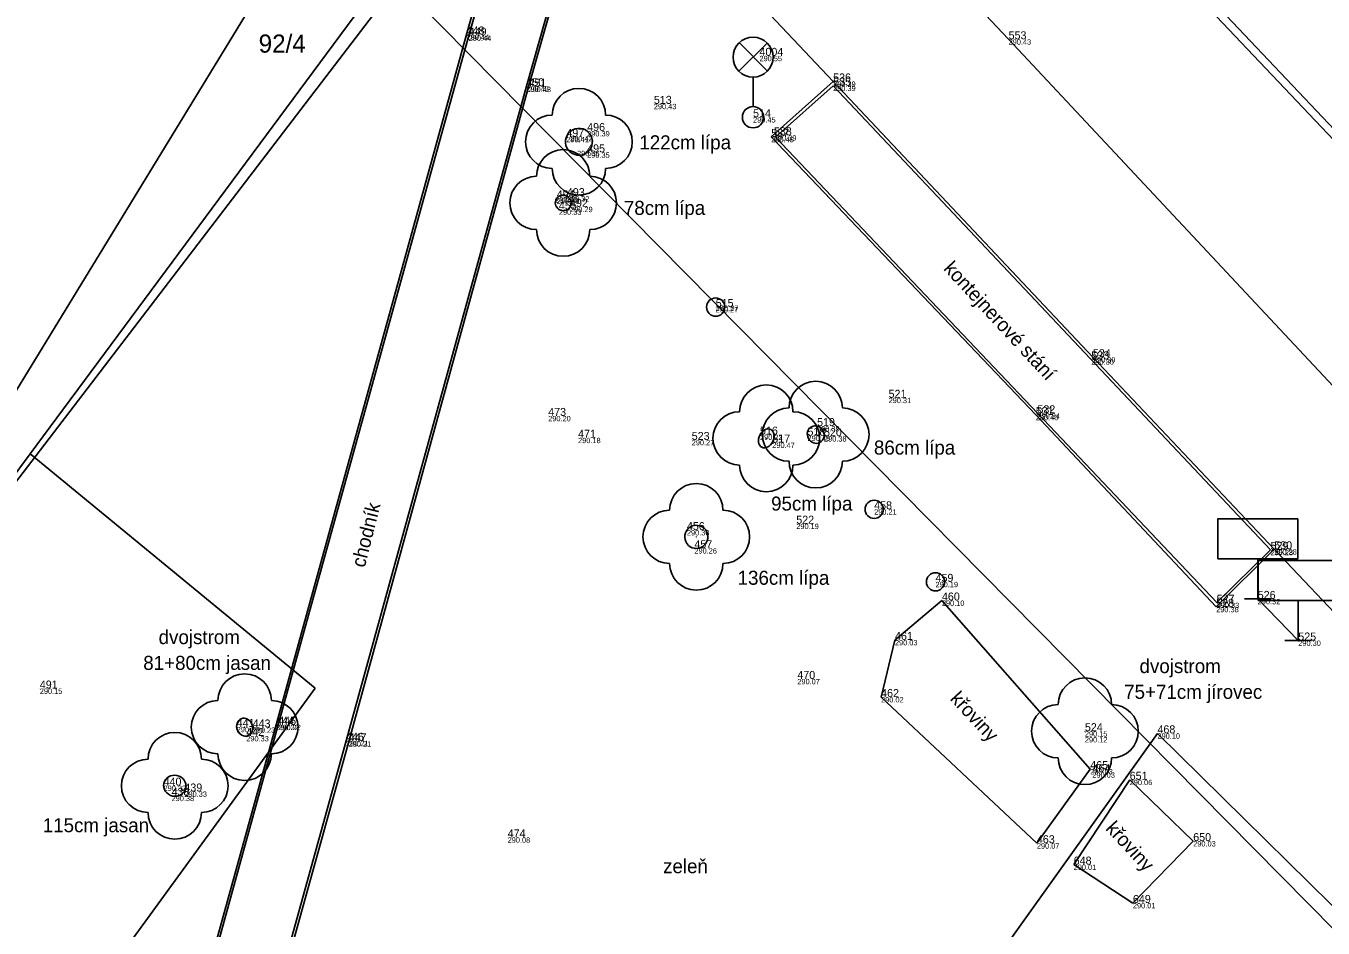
# Model space of a CAD drawing. Extents: x -805057 to -804930, y -994399 to -994240.
# Drawn here: x -805024.17 to -804999.86, y -994284.05 to -994267.14 of the extents above; entities that cross this region are included whole.
import ezdxf

# ---------------------------------------------------------------- set-up
doc = ezdxf.new("R2010")
doc.units = 0
for name, color, linetype in [('bod cislo', 7, 'Continuous'), ('bod pozice', 7, 'Continuous'), ('bod výška', 7, 'Continuous'), ('Katastralni mapa', 7, 'Continuous'), ('komunikace', 7, 'Continuous'), ('lampa', 7, 'Continuous'), ('plot', 7, 'Continuous'), ('popis', 7, 'Continuous'), ('sloupek', 7, 'Continuous'), ('strom', 7, 'Continuous'), ('značka', 7, 'Continuous')]:
    doc.layers.add(name, color=color, linetype=linetype)

msp = doc.modelspace()

# ---------------------------------------------------------------- linework, layer by layer
at = {"layer": 'bod pozice'}
for p, q in [((-805015.91, -994267.3), (-805015.91, -994267.3)), ((-805015.87, -994267.32), (-805015.87, -994267.32)), ((-805005.75, -994267.39), (-805005.75, -994267.39)), ((-805010.42, -994267.7), (-805010.42, -994267.7)), ((-805014.79, -994268.27), (-805014.79, -994268.27)), ((-805014.75, -994268.28), (-805014.75, -994268.28)), ((-805009.04, -994268.18), (-805009.04, -994268.18)), ((-805009.04, -994268.26), (-805009.04, -994268.26)), ((-805012.4, -994268.6), (-805012.4, -994268.6)), ((-805010.54, -994268.85), (-805010.54, -994268.85)), ((-805013.65, -994269.11), (-805013.65, -994269.11)), ((-805014.04, -994269.22), (-805014.04, -994269.22)), ((-805010.2, -994269.22), (-805010.2, -994269.22)), ((-805010.15, -994269.19), (-805010.15, -994269.19)), ((-805013.65, -994269.51), (-805013.65, -994269.51)), ((-805014.03, -994270.33), (-805014.03, -994270.33)), ((-805014.22, -994270.37), (-805014.22, -994270.37)), ((-805014.18, -994270.58), (-805014.18, -994270.58)), ((-805013.97, -994270.53), (-805013.97, -994270.53)), ((-805011.24, -994272.41), (-805011.24, -994272.41)), ((-805004.2, -994273.39), (-805004.2, -994273.39)), ((-805004.17, -994273.35), (-805004.17, -994273.35)), ((-805008, -994274.11), (-805008, -994274.11)), ((-805014.38, -994274.45), (-805014.38, -994274.45)), ((-805005.24, -994274.43), (-805005.24, -994274.43)), ((-805005.21, -994274.4), (-805005.21, -994274.4)), ((-805009.34, -994274.64), (-805009.34, -994274.64)), ((-805013.82, -994274.86), (-805013.82, -994274.86)), ((-805011.69, -994274.9), (-805011.69, -994274.9)), ((-805010.41, -994274.8), (-805010.41, -994274.8)), ((-805010.18, -994274.95), (-805010.18, -994274.95)), ((-805009.52, -994274.82), (-805009.52, -994274.82)), ((-805009.21, -994274.83), (-805009.21, -994274.83)), ((-805008.27, -994276.2), (-805008.27, -994276.2)), ((-805011.78, -994276.59), (-805011.78, -994276.59)), ((-805009.73, -994276.47), (-805009.73, -994276.47)), ((-805011.64, -994276.93), (-805011.64, -994276.93)), ((-805000.84, -994276.96), (-805000.84, -994276.96)), ((-805000.77, -994276.95), (-805000.77, -994276.95)), ((-805007.12, -994277.56), (-805007.12, -994277.56)), ((-805001.08, -994277.88), (-805001.08, -994277.88)), ((-805007, -994277.91), (-805007, -994277.91)), ((-805001.86, -994278.03), (-805001.86, -994278.03)), ((-805001.85, -994277.95), (-805001.85, -994277.95)), ((-805007.88, -994278.65), (-805007.88, -994278.65)), ((-805000.32, -994278.66), (-805000.32, -994278.66)), ((-805023.91, -994279.56), (-805023.91, -994279.56)), ((-805009.71, -994279.38), (-805009.71, -994279.38)), ((-805008.14, -994279.72), (-805008.14, -994279.72)), ((-805020.22, -994280.28), (-805020.22, -994280.28)), ((-805019.92, -994280.29), (-805019.92, -994280.29)), ((-805019.48, -994280.24), (-805019.48, -994280.24)), ((-805019.44, -994280.24), (-805019.44, -994280.24)), ((-805020.04, -994280.45), (-805020.04, -994280.45)), ((-805018.17, -994280.54), (-805018.17, -994280.54)), ((-805018.12, -994280.55), (-805018.12, -994280.55)), ((-805004.32, -994280.36), (-805004.32, -994280.36)), ((-805002.96, -994280.4), (-805002.96, -994280.4)), ((-805004.22, -994281.07), (-805004.22, -994281.07)), ((-805004.18, -994281.13), (-805004.18, -994281.13)), ((-805003.48, -994281.27), (-805003.48, -994281.27)), ((-805021.59, -994281.38), (-805021.59, -994281.38)), ((-805021.2, -994281.49), (-805021.2, -994281.49)), ((-805021.44, -994281.57), (-805021.44, -994281.57)), ((-805015.14, -994282.35), (-805015.14, -994282.35)), ((-805005.22, -994282.46), (-805005.22, -994282.46)), ((-805002.29, -994282.42), (-805002.29, -994282.42)), ((-805004.53, -994282.86), (-805004.53, -994282.86)), ((-805003.42, -994283.58), (-805003.42, -994283.58))]:
    msp.add_line(p, q, dxfattribs=at)
at = {"layer": 'Katastralni mapa'}
for points in [[(-805018.71, -994264.73), (-805029.78, -994282.86)], [(-805017.39, -994266.11), (-805024.09, -994275.16)], [(-805017.39, -994266.11), (-804988.46, -994295.41)], [(-805024.09, -994275.16), (-805029.78, -994282.86)], [(-805024.09, -994275.16), (-805018.75, -994279.55)], [(-805018.75, -994279.55), (-805023.45, -994286.01)]]:
    msp.add_lwpolyline(points, dxfattribs=at)
at = {"layer": 'komunikace'}
for p, q in [((-805014.33, -994253.78), (-804993.36, -994275.93)), ((-804993.27, -994275.83), (-805014.23, -994253.66)), ((-805005.75, -994267.39), (-805015.94, -994256.52)), ((-805015.91, -994267.3), (-805014.52, -994262.4)), ((-805014.487, -994262.435), (-805015.87, -994267.32)), ((-805014.79, -994268.27), (-805013.45, -994263.54)), ((-805013.4, -994263.56), (-805014.75, -994268.28)), ((-805009.04, -994268.18), (-805013.4, -994263.56)), ((-805019.48, -994280.24), (-805015.91, -994267.3)), ((-805015.87, -994267.32), (-805019.44, -994280.24)), ((-804985.37, -994289.18), (-805005.75, -994267.39)), ((-805018.17, -994280.54), (-805014.79, -994268.27)), ((-805014.75, -994268.28), (-805018.12, -994280.55)), ((-805009.04, -994268.18), (-805010.2, -994269.22)), ((-805009.04, -994268.26), (-805010.117, -994269.225)), ((-805004.17, -994273.35), (-805009.04, -994268.18)), ((-805009.04, -994268.26), (-805000.84, -994276.96)), ((-805010.2, -994269.22), (-805005.24, -994274.43)), ((-805005.21, -994274.4), (-805010.117, -994269.225)), ((-805000.77, -994276.95), (-805004.17, -994273.35)), ((-805005.24, -994274.43), (-805001.86, -994278.03)), ((-805001.85, -994277.95), (-805005.21, -994274.4)), ((-805001.86, -994278.03), (-805000.77, -994276.95)), ((-805000.84, -994276.96), (-805001.85, -994277.95)), ((-804995.24, -994282.79), (-805000.77, -994276.95)), ((-805022.78, -994292.15), (-805019.48, -994280.24)), ((-805019.44, -994280.24), (-805022.73, -994292.16)), ((-805021.58, -994292.88), (-805018.17, -994280.54)), ((-805018.12, -994280.55), (-805021.54, -994292.91))]:
    msp.add_line(p, q, dxfattribs=at)
at = {"layer": 'lampa'}
for p, q in [((-805010.804, -994267.988), (-805010.276, -994267.46)), ((-805010.804, -994267.988), (-805010.276, -994267.46)), ((-805010.268, -994267.985), (-805010.796, -994267.456)), ((-805010.268, -994267.985), (-805010.796, -994267.456)), ((-805010.54, -994268.65), (-805010.54, -994268.1)), ((-805010.54, -994268.65), (-805010.54, -994268.1))]:
    msp.add_line(p, q, dxfattribs=at)
for centre, radius in [((-805010.54, -994267.725), 0.375), ((-805010.54, -994267.725), 0.375), ((-805010.54, -994268.85), 0.2), ((-805010.54, -994268.85), 0.2)]:
    msp.add_circle(centre, radius, dxfattribs=at)
at = {"layer": 'plot'}
for p, q in [((-805002.96, -994280.4), (-805015.07, -994297.35)), ((-804992.39, -994290.82), (-805002.96, -994280.4))]:
    msp.add_line(p, q, dxfattribs=at)
msp.add_lwpolyline([(-805032.38, -994286.17), (-805016.94, -994265.99), (-805019.51, -994262.99)], dxfattribs=at)
at = {"layer": 'sloupek'}
for centre in [(-805011.24, -994272.41), (-805011.24, -994272.41), (-805008.27, -994276.2), (-805008.27, -994276.2), (-805007.12, -994277.56), (-805007.12, -994277.56)]:
    msp.add_circle(centre, 0.171, dxfattribs=at)
at = {"layer": 'strom'}
for p, q in [((-805007, -994277.91), (-805007.88, -994278.65)), ((-805004.22, -994281.07), (-805007, -994277.91)), ((-805007.88, -994278.65), (-805008.14, -994279.72)), ((-805008.14, -994279.72), (-805005.22, -994282.46)), ((-805005.22, -994282.46), (-805004.22, -994281.07)), ((-805003.48, -994281.27), (-805004.53, -994282.86)), ((-805002.29, -994282.42), (-805003.48, -994281.27)), ((-805003.42, -994283.58), (-805002.29, -994282.42)), ((-805004.53, -994282.86), (-805003.42, -994283.58))]:
    msp.add_line(p, q, dxfattribs=at)
for centre in [(-805013.805, -994269.311), (-805014.1, -994270.457), (-805010.292, -994274.87), (-805009.366, -994274.8), (-805011.604, -994276.716), (-805020.07, -994280.284), (-805004.32, -994280.36), (-805021.38, -994281.383)]:
    msp.add_circle(centre, 0.0005, dxfattribs=at)
for centre, start, end in [((-805013.805, -994268.811), 0, 180), ((-805014.305, -994269.311), 90, 270), ((-805013.305, -994269.311), 270, 90), ((-805014.1, -994269.957), 0, 180), ((-805013.805, -994269.811), 180, 360), ((-805014.6, -994270.457), 90, 270), ((-805013.6, -994270.457), 270, 90), ((-805014.1, -994270.957), 180, 360), ((-805010.292, -994274.37), 0, 180), ((-805009.366, -994274.3), 0, 180), ((-805010.792, -994274.87), 90, 270), ((-805009.866, -994274.8), 90, 270), ((-805009.792, -994274.87), 270, 90), ((-805008.866, -994274.8), 270, 90), ((-805010.292, -994275.37), 180, 360), ((-805009.366, -994275.3), 180, 360), ((-805011.604, -994276.216), 0, 180), ((-805012.104, -994276.716), 90, 270), ((-805011.104, -994276.716), 270, 90), ((-805011.604, -994277.216), 180, 360), ((-805020.07, -994279.784), 0, 180), ((-805004.32, -994279.86), 0, 180), ((-805020.57, -994280.284), 90, 270), ((-805019.57, -994280.284), 270, 90), ((-805004.82, -994280.36), 90, 270), ((-805003.82, -994280.36), 270, 90), ((-805021.38, -994280.883), 0, 180), ((-805020.07, -994280.784), 180, 360), ((-805021.88, -994281.383), 90, 270), ((-805020.88, -994281.383), 270, 90), ((-805004.32, -994280.86), 180, 360), ((-805021.38, -994281.883), 180, 360)]:
    msp.add_arc(centre, 0.5, start, end, dxfattribs=at)
for centre, major_axis, ratio in [((-805013.805, -994269.311), (0.199, 0.158), 0.991939), ((-805014.1, -994270.457), (-0.125, 0.08), 0.976561), ((-805010.292, -994274.87), (0.083, 0.166), 0.737215), ((-805009.366, -994274.8), (-0.079, 0.147), 0.925208), ((-805011.604, -994276.716), (0.176, 0.128), 0.993787), ((-805020.07, -994280.284), (0.064, -0.158), 0.863711), ((-805021.38, -994281.383), (0.206, -0.044), 0.932012)]:
    msp.add_ellipse(centre, major_axis=major_axis, ratio=ratio, dxfattribs=at)
at = {"layer": 'značka'}
for p, q in [((-805001.08, -994277.13), (-805001.08, -994277.88)), ((-805001.33, -994277.88), (-805000.83, -994277.88)), ((-805000.32, -994278.66), (-805001.08, -994277.88)), ((-805000.32, -994277.91), (-805000.32, -994278.66)), ((-805000.57, -994278.66), (-805000.07, -994278.66))]:
    msp.add_line(p, q, dxfattribs=at)
for points in [[(-805001.83, -994277.13), (-805000.33, -994277.13), (-805000.33, -994276.38), (-805001.83, -994276.38)], [(-805001.07, -994277.91), (-804999.57, -994277.91), (-804999.57, -994277.16), (-805001.07, -994277.16)]]:
    msp.add_lwpolyline(points, close=True, dxfattribs=at)

# ---------------------------------------------------------------- texts
at = {"layer": 'bod cislo'}
for s, p in [('448    ', (-805015.91, -994267.3)), ('449    ', (-805015.87, -994267.32)), ('553    ', (-805005.75, -994267.39)), ('4004    ', (-805010.42, -994267.7)), ('450    ', (-805014.79, -994268.27)), ('451    ', (-805014.75, -994268.28)), ('536    ', (-805009.04, -994268.18)), ('535    ', (-805009.04, -994268.26)), ('513    ', (-805012.4, -994268.6)), ('514    ', (-805010.54, -994268.85)), ('497    ', (-805014.04, -994269.22)), ('496    ', (-805013.65, -994269.11)), ('537    ', (-805010.2, -994269.22)), ('538    ', (-805010.15, -994269.19)), ('495    ', (-805013.65, -994269.51)), ('494    ', (-805014.22, -994270.37)), ('493    ', (-805014.03, -994270.33)), ('455    ', (-805014.18, -994270.58)), ('492    ', (-805013.97, -994270.53)), ('515    ', (-805011.24, -994272.41)), ('533    ', (-805004.2, -994273.39)), ('534    ', (-805004.17, -994273.35)), ('521    ', (-805008, -994274.11)), ('532    ', (-805005.21, -994274.4)), ('473    ', (-805014.38, -994274.45)), ('519    ', (-805009.34, -994274.64)), ('531    ', (-805005.24, -994274.43)), ('471    ', (-805013.82, -994274.86)), ('516    ', (-805010.41, -994274.8)), ('518    ', (-805009.52, -994274.82)), ('520    ', (-805009.21, -994274.83)), ('523    ', (-805011.69, -994274.9)), ('517    ', (-805010.18, -994274.95)), ('458    ', (-805008.27, -994276.2)), ('522    ', (-805009.73, -994276.47)), ('456    ', (-805011.78, -994276.59)), ('457    ', (-805011.64, -994276.93)), ('529    ', (-805000.84, -994276.96)), ('530    ', (-805000.77, -994276.95)), ('459    ', (-805007.12, -994277.56)), ('460    ', (-805007, -994277.91)), ('528    ', (-805001.86, -994278.03)), ('527    ', (-805001.85, -994277.95)), ('526    ', (-805001.08, -994277.88)), ('461    ', (-805007.88, -994278.65)), ('525    ', (-805000.32, -994278.66)), ('470    ', (-805009.71, -994279.38)), ('491    ', (-805023.91, -994279.56)), ('462    ', (-805008.14, -994279.72)), ('441    ', (-805020.22, -994280.28)), ('442    ', (-805020.04, -994280.45)), ('443    ', (-805019.92, -994280.29)), ('444    ', (-805019.48, -994280.24)), ('445    ', (-805019.44, -994280.24)), ('524    ', (-805004.32, -994280.36)), ('468    ', (-805002.96, -994280.4)), ('446    ', (-805018.17, -994280.54)), ('447    ', (-805018.12, -994280.55)), ('465    ', (-805004.22, -994281.07)), ('464    ', (-805004.18, -994281.13)), ('440    ', (-805021.59, -994281.38)), ('651    ', (-805003.48, -994281.27)), ('438    ', (-805021.44, -994281.57)), ('439    ', (-805021.2, -994281.49)), ('474    ', (-805015.14, -994282.35)), ('650    ', (-805002.29, -994282.42)), ('463    ', (-805005.22, -994282.46)), ('648    ', (-805004.53, -994282.86)), ('649    ', (-805003.42, -994283.58))]:
    msp.add_text(s, height=0.15, dxfattribs=at).set_placement(p)
at = {"layer": 'bod výška'}
for s, p in [('290.44  ', (-805015.91, -994267.4)), ('290.44  ', (-805015.87, -994267.42)), ('290.43  ', (-805005.75, -994267.49)), ('290.55  ', (-805010.42, -994267.8)), ('290.43  ', (-805014.79, -994268.37)), ('290.43  ', (-805014.75, -994268.38)), ('290.39  ', (-805009.04, -994268.28)), ('290.39  ', (-805009.04, -994268.36)), ('290.43  ', (-805012.4, -994268.7)), ('290.45  ', (-805010.54, -994268.95)), ('290.39  ', (-805013.65, -994269.21)), ('290.41  ', (-805014.04, -994269.32)), ('290.42  ', (-805013.97, -994269.3)), ('290.45  ', (-805010.2, -994269.32)), ('290.39  ', (-805010.15, -994269.29)), ('290.36  ', (-805013.84, -994269.58)), ('290.35  ', (-805013.65, -994269.61)), ('290.30  ', (-805014.25, -994270.45)), ('290.32  ', (-805014.03, -994270.43)), ('290.29  ', (-805014.22, -994270.47)), ('290.33  ', (-805014.18, -994270.68)), ('290.29  ', (-805013.97, -994270.63)), ('290.27  ', (-805011.24, -994272.48)), ('290.27  ', (-805011.24, -994272.51)), ('290.30  ', (-805004.2, -994273.49)), ('290.30  ', (-805004.17, -994273.45)), ('290.31  ', (-805008, -994274.21)), ('290.20  ', (-805014.38, -994274.55)), ('290.40  ', (-805005.24, -994274.53)), ('290.34  ', (-805005.21, -994274.5)), ('290.39  ', (-805009.34, -994274.74)), ('290.18  ', (-805013.82, -994274.96)), ('290.27  ', (-805011.69, -994275)), ('290.22  ', (-805010.41, -994274.9)), ('290.47  ', (-805010.18, -994275.05)), ('290.49  ', (-805009.52, -994274.92)), ('290.38  ', (-805009.21, -994274.93)), ('290.21  ', (-805008.27, -994276.3)), ('290.30  ', (-805011.78, -994276.69)), ('290.19  ', (-805009.73, -994276.57)), ('290.26  ', (-805011.64, -994277.03)), ('290.28  ', (-805000.84, -994277.06)), ('290.28  ', (-805000.77, -994277.05)), ('290.19  ', (-805007.12, -994277.66)), ('290.32  ', (-805001.08, -994277.98)), ('290.10  ', (-805007, -994278.01)), ('290.38  ', (-805001.86, -994278.13)), ('290.33  ', (-805001.85, -994278.05)), ('290.03  ', (-805007.88, -994278.75)), ('290.30  ', (-805000.32, -994278.76)), ('290.15  ', (-805023.91, -994279.66)), ('290.07  ', (-805009.71, -994279.48)), ('290.02  ', (-805008.14, -994279.82)), ('290.39  ', (-805020.22, -994280.38)), ('290.23  ', (-805019.92, -994280.39)), ('290.22  ', (-805019.48, -994280.34)), ('290.22  ', (-805019.44, -994280.34)), ('290.33  ', (-805020.04, -994280.55)), ('290.21  ', (-805018.17, -994280.64)), ('290.21  ', (-805018.12, -994280.65)), ('290.15  ', (-805004.32, -994280.46)), ('290.12  ', (-805004.32, -994280.57)), ('290.12  ', (-805004.32, -994280.57)), ('290.10  ', (-805002.96, -994280.5)), ('290.03  ', (-805004.22, -994281.17)), ('290.03  ', (-805004.18, -994281.23)), ('290.06  ', (-805003.48, -994281.37)), ('290.32  ', (-805021.59, -994281.48)), ('290.33  ', (-805021.2, -994281.59)), ('290.38  ', (-805021.44, -994281.67)), ('290.08  ', (-805015.14, -994282.45)), ('290.07  ', (-805005.22, -994282.56)), ('290.03  ', (-805002.29, -994282.52)), ('290.01  ', (-805004.53, -994282.96)), ('290.01  ', (-805003.42, -994283.68))]:
    msp.add_text(s, height=0.1, dxfattribs=at).set_placement(p)
at = {"layer": 'Katastralni mapa'}
msp.add_text('92/4', height=0.34, dxfattribs=at).set_placement((-805019.808, -994267.64))
at = {"layer": 'popis'}
for s, height, p in [('122cm lípa', 0.2629, (-805012.672, -994269.453)), ('78cm lípa', 0.2629, (-805012.962, -994270.681)), ('86cm lípa', 0.2629, (-805008.275, -994275.174)), ('95cm lípa', 0.2629, (-805010.202, -994276.224)), ('136cm lípa', 0.2629, (-805010.83, -994277.615)), ('dvojstrom', 0.2629, (-805021.683, -994278.727)), ('81+80cm jasan', 0.26289, (-805021.971, -994279.21)), ('dvojstrom', 0.2629, (-805003.296, -994279.27)), ('75+71cm jírovec', 0.26289, (-805003.584, -994279.753)), ('115cm jasan', 0.26289, (-805023.855, -994282.253)), ('zeleň', 0.2629, (-805012.227, -994283.021))]:
    msp.add_text(s, height=height, dxfattribs=at).set_placement(p)
for s, height, rotation, p in [('kontejnerové stání', 0.26289, 312.8096, (-805006.983, -994271.7)), ('chodník', 0.2629, 75.983, (-805017.82, -994277.306)), ('křoviny', 0.2629, 312.8096, (-805006.862, -994279.763)), ('křoviny', 0.2629, 312.8096, (-805003.947, -994282.195))]:
    msp.add_text(s, height=height, rotation=rotation, dxfattribs=at).set_placement(p)

doc.saveas('drawing.dxf')
